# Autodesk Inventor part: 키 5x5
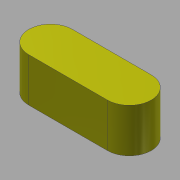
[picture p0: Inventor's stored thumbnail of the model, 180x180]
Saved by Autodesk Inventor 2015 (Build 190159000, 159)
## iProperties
Created: 2016-04
Part Number: 키 5x5
Document SubType Name: Modeling
Designer: mdu
Density: 7.86 g/cm^3
Mass: 2.54015 g
Surface Area: 2.9781 cm^2
Volume: 0.323175 cm^3
Material: 강철, 연강
Appearance: 강철 - 광택
Author: mdu
Revision Number: 1
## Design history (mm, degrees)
sketch "스케치1"
  geometry: L1 (-4.5, -2.5)-(4.5, -2.5); L2 (4.5, 2.5)-(-4.5, 2.5); A1 r 2.5 centre (4.5, 0) between (4.5, -2.5) and (4.5, 2.5); A2 r 2.5 centre (-4.5, 0) between (-4.5, 2.5) and (-4.5, -2.5); 2 further points
  constraints: 4 end point, 4 point on circle, 4 tangent, 2 centre point, 1 horizontal, 1 horizontal alignment, 1 midpoint, 1 parallel, 1 vertical alignment
  dimensions: "d0" = 5 distance between parallel lines of L1 L2; "d1" = 14 dimension on A1 A2
extrude "돌출1" new body sketch "스케치1" stored distance "d2" = 5; taper "d3" = 0 deg
node "솔리드1"
